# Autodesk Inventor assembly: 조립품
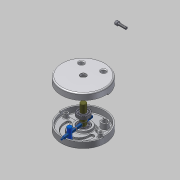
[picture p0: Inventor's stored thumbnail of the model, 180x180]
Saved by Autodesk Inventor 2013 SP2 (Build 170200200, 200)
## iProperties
Created: 2015-04
Part Number: 조립품
Document SubType Name: Assembly
Designer: dgall
Author: dgall
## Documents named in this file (10)
- C:\Documents and Settings\dgall\바탕 화면\450405v1018\조립품.iam
- C:\Documents and Settings\dgall\바탕 화면\450405v1018\본체.ipt
- C:\Documents and Settings\dgall\바탕 화면\450405v1018\덮개.ipt
- C:\Documents and Settings\dgall\바탕 화면\450405v1018\멈춤링.ipt
- C:\Documents and Settings\dgall\바탕 화면\450405v1018\베어링62_22.ipt
- C:\Documents and Settings\dgall\바탕 화면\450405v1018\슬라이더.ipt
- C:\Documents and Settings\dgall\바탕 화면\450405v1018\슬라이더2.ipt
- C:\Documents and Settings\dgall\바탕 화면\450405v1018\축.ipt
- C:\Documents and Settings\dgall\바탕 화면\450405v1018\평행핀.ipt
- C:\Documents and Settings\dgall\바탕 화면\450405v1018\M 10 x 35.ipt
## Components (1 placed, 1 different names)
1. M 10 x 35:1
